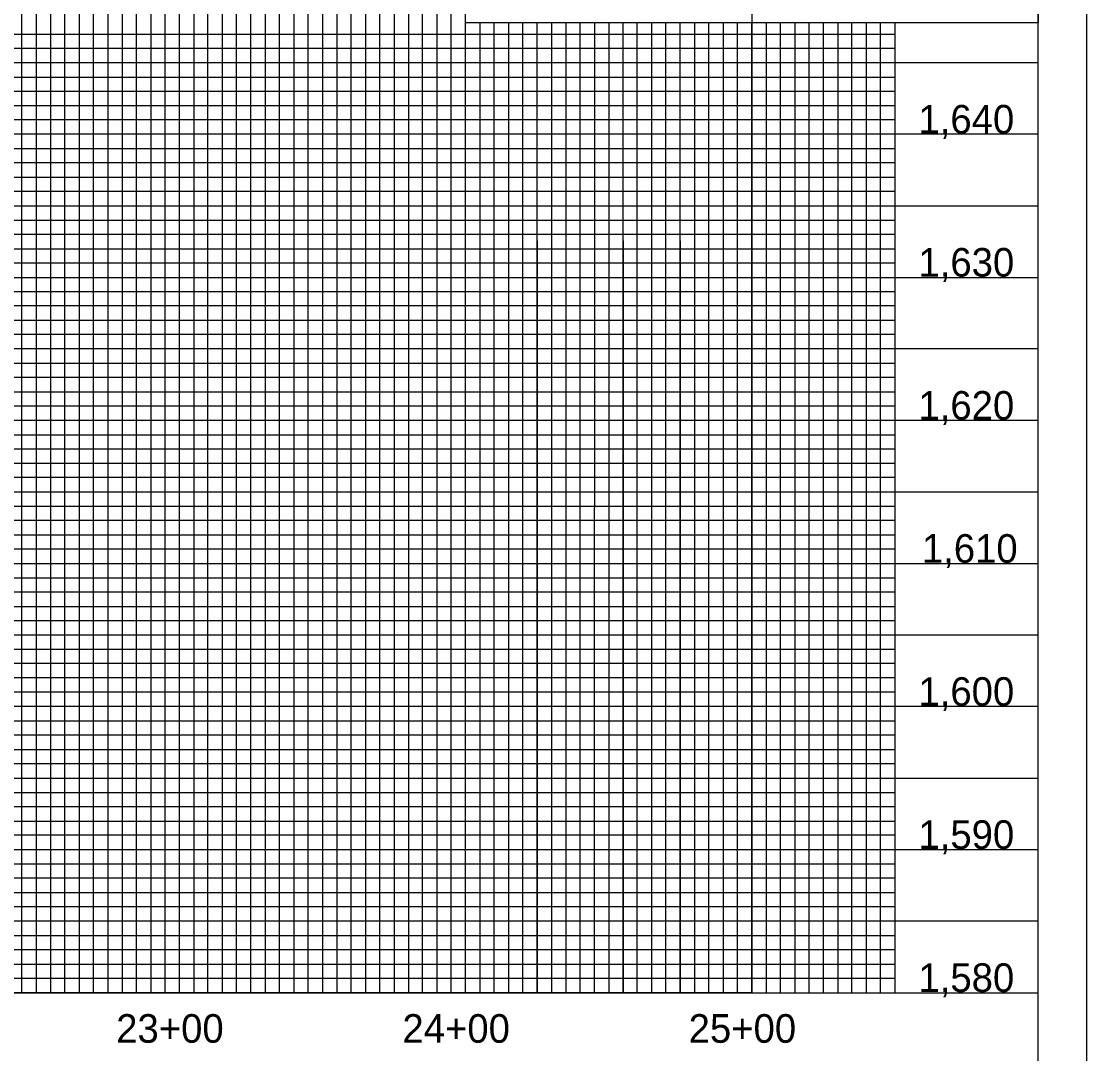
# Model space of a CAD drawing. Extents: x 502400 to 509344, y 448070 to 484209.
# Drawn here: x 506913.9 to 507286.1, y 483662.4 to 484023.2 of the extents above; entities that cross this region are included whole.
import ezdxf

# ---------------------------------------------------------------- set-up
doc = ezdxf.new("R2010")
doc.units = 0
for name, color, linetype in [('Exist Vertical Profile Vertical Axis Label', 7, 'Continuous'), ('Sheet Layout Profile Border Port 1', 7, 'Continuous'), ('Sheet Plot Border Outside CELL', 7, 'Continuous'), ('Sheet Profile CELL', 7, 'Continuous'), ('Sheet Profile Grid Major CELL', 7, 'Continuous'), ('Sheet Profile Grid Middle CELL', 7, 'Continuous'), ('Sheet Profile Grid Minor CELL', 7, 'Continuous'), ('Sheet Sticker Exception Certification CELL', 7, 'Continuous')]:
    doc.layers.add(name, color=color, linetype=linetype)

msp = doc.modelspace()

# ---------------------------------------------------------------- linework, layer by layer
at = {"layer": 'Sheet Layout Profile Border Port 1'}
msp.add_lwpolyline([(506419.08, 484183.71), (507169.08, 484183.71), (507169.08, 483683.71), (506419.08, 483683.71)], close=True, dxfattribs=at)
at = {"layer": 'Sheet Plot Border Outside CELL'}
msp.add_lwpolyline([(505602.08, 483108.71), (507286.08, 483108.71), (507286.08, 484208.71), (505602.08, 484208.71)], close=True, dxfattribs=at)
at = {"layer": 'Sheet Profile CELL'}
msp.add_line((505769.08, 483683.71), (507269.08, 483683.71), dxfattribs=at)
msp.add_lwpolyline([(507269.08, 484183.71), (505769.08, 484183.71), (505769.08, 483133.71), (507269.08, 483133.71)], close=True, dxfattribs=at)
at = {"layer": 'Sheet Profile Grid Major CELL'}
for points in [[(506519.08, 483683.71), (506569.08, 483683.71), (506569.08, 484183.71), (506619.08, 484183.71), (506619.08, 483683.71), (506669.08, 483683.71), (506669.08, 484183.71), (506719.08, 484183.71), (506719.08, 483683.71), (506769.08, 483683.71), (506769.08, 484183.71), (506819.08, 484183.71), (506819.08, 483683.71), (506869.08, 483683.71), (506869.08, 484183.71), (506919.08, 484183.71), (506919.08, 483683.71), (506969.08, 483683.71), (506969.08, 484183.71), (507019.08, 484183.71), (507019.08, 483683.71), (507069.08, 483683.71), (507069.08, 484183.71), (507095.38, 484183.71)], [(507219.08, 484022.66), (507219.08, 483683.71), (507269.08, 483683.71), (507269.08, 484033.71)], [(507119.08, 484022.66), (507119.08, 483683.71), (507169.08, 483683.71), (507169.08, 483683.71), (507169.08, 484022.66)], [(507269.08, 483983.71), (505769.08, 483983.71), (505769.08, 483933.71), (507269.08, 483933.71)], [(507269.08, 483883.71), (505769.08, 483883.71), (505769.08, 483833.71), (507269.08, 483833.71)], [(507269.08, 483783.71), (505769.08, 483783.71), (505769.08, 483783.71), (505769.08, 483733.71), (507269.08, 483733.71)]]:
    msp.add_lwpolyline(points, dxfattribs=at)
at = {"layer": 'Sheet Profile Grid Middle CELL'}
for points in [[(506894.08, 484183.71), (506944.08, 484183.71), (506944.08, 483683.71), (506994.08, 483683.71), (506994.08, 484183.71), (507044.08, 484183.71), (507044.08, 483683.71), (507094.08, 483683.71), (507094.08, 484022.66)], [(507094.08, 483946.51), (507094.08, 483683.71), (507144.08, 483683.71), (507144.08, 484022.66)], [(507144.08, 483946.51), (507144.08, 483683.71), (507194.08, 483683.71), (507194.08, 484022.66)], [(507269.08, 484008.71), (505769.08, 484008.71), (505769.08, 483958.71), (507094.08, 483958.71)], [(507094.08, 483958.71), (507269.08, 483958.71)], [(507269.08, 483908.71), (505769.08, 483908.71), (505769.08, 483858.71), (507269.08, 483858.71)], [(507269.08, 483808.71), (505769.08, 483808.71), (505769.08, 483758.71), (507269.08, 483758.71)], [(507269.08, 483708.71), (505769.08, 483708.71)]]:
    msp.add_lwpolyline(points, dxfattribs=at)
at = {"layer": 'Sheet Profile Grid Minor CELL'}
for p, q in [((505819.08, 484018.71), (507219.08, 484018.71)), ((507219.08, 483998.71), (505819.08, 483998.71)), ((505819.08, 483993.71), (507219.08, 483993.71)), ((507219.08, 483973.71), (505819.08, 483973.71)), ((505819.08, 483968.71), (507219.08, 483968.71)), ((507219.08, 483948.71), (505819.08, 483948.71)), ((505819.08, 483943.71), (507219.08, 483943.71)), ((507219.08, 483938.71), (505819.08, 483938.71)), ((505819.08, 483928.71), (507219.08, 483928.71)), ((507219.08, 483923.71), (505819.08, 483923.71)), ((505819.08, 483918.71), (507219.08, 483918.71)), ((507219.08, 483913.71), (505819.08, 483913.71)), ((505819.08, 483903.71), (507219.08, 483903.71)), ((507219.08, 483898.71), (505819.08, 483898.71)), ((505819.08, 483893.71), (507219.08, 483893.71)), ((507219.08, 483888.71), (505819.08, 483888.71)), ((505819.08, 483878.71), (507219.08, 483878.71)), ((507219.08, 483873.71), (505819.08, 483873.71)), ((505819.08, 483868.71), (507219.08, 483868.71)), ((507219.08, 483863.71), (505819.08, 483863.71)), ((505819.08, 483853.71), (507219.08, 483853.71)), ((507219.08, 483848.71), (505819.08, 483848.71)), ((505819.08, 483843.71), (507219.08, 483843.71)), ((507219.08, 483838.71), (505819.08, 483838.71)), ((505819.08, 483828.71), (507219.08, 483828.71)), ((507219.08, 483823.71), (505819.08, 483823.71)), ((505819.08, 483818.71), (507219.08, 483818.71)), ((507219.08, 483813.71), (505819.08, 483813.71)), ((505819.08, 483803.71), (507219.08, 483803.71)), ((507219.08, 483798.71), (505819.08, 483798.71)), ((507219.08, 483793.71), (505819.08, 483793.71)), ((507219.08, 483788.71), (505819.08, 483788.71)), ((505819.08, 483778.71), (507219.08, 483778.71)), ((507219.08, 483773.71), (505819.08, 483773.71)), ((505819.08, 483768.71), (507219.08, 483768.71)), ((507219.08, 483763.71), (505819.08, 483763.71)), ((505819.08, 483753.71), (507219.08, 483753.71)), ((507219.08, 483748.71), (505819.08, 483748.71)), ((505819.08, 483743.71), (507219.08, 483743.71)), ((507219.08, 483738.71), (505819.08, 483738.71)), ((505819.08, 483728.71), (507219.08, 483728.71)), ((507219.08, 483723.71), (505819.08, 483723.71)), ((505819.08, 483718.71), (507219.08, 483718.71)), ((507219.08, 483713.71), (505819.08, 483713.71)), ((505819.08, 483703.71), (507219.08, 483703.71)), ((507219.08, 483698.71), (505819.08, 483698.71)), ((505819.08, 483693.71), (507219.08, 483693.71))]:
    msp.add_line(p, q, dxfattribs=at)
for points in [[(506909.08, 483683.71), (506914.08, 483683.71), (506914.08, 484183.71), (506924.08, 484183.71), (506924.08, 483683.71), (506929.08, 483683.71), (506929.08, 484183.71), (506934.08, 484183.71), (506934.08, 483683.71), (506939.08, 483683.71), (506939.08, 484183.71), (506949.08, 484183.71), (506949.08, 483683.71), (506954.08, 483683.71), (506954.08, 484183.71), (506959.08, 484183.71), (506959.08, 483683.71)], [(506959.08, 483683.71), (506964.08, 483683.71), (506964.08, 484183.71)], [(506974.08, 484183.71), (506974.08, 483683.71), (506979.08, 483683.71), (506979.08, 484183.71)], [(506984.08, 484183.71), (506984.08, 483683.71), (506989.08, 483683.71), (506989.08, 484183.71)], [(506999.08, 484183.71), (506999.08, 483683.71), (507004.08, 483683.71), (507004.08, 484183.71)], [(507009.08, 484183.71), (507009.08, 483683.71), (507014.08, 483683.71), (507014.08, 484183.71)], [(507024.08, 484183.71), (507024.08, 483683.71), (507029.08, 483683.71), (507029.08, 484183.71)], [(507034.08, 484183.71), (507034.08, 483683.71), (507039.08, 483683.71), (507039.08, 484183.71)], [(507049.08, 484183.71), (507049.08, 483683.71), (507054.08, 483683.71), (507054.08, 484183.71)], [(507059.08, 484183.71), (507059.08, 483683.71), (507064.08, 483683.71), (507064.08, 484183.71)], [(507074.08, 484022.66), (507074.08, 483683.71), (507079.08, 483683.71), (507079.08, 484022.66)], [(507084.08, 484022.66), (507084.08, 483683.71), (507089.08, 483683.71), (507089.08, 484022.66)], [(507099.08, 484022.66), (507099.08, 483683.71), (507099.08, 483683.71), (507104.08, 483683.71), (507109.08, 483683.71), (507109.08, 484022.66)], [(507104.08, 484022.66), (507104.08, 483683.71)], [(507114.07, 484022.66), (507113.98, 483683.76), (507118.98, 483683.76), (507124.08, 483683.71), (507124.08, 484022.66)], [(507124.08, 483946.51), (507124.08, 483683.71), (507129.08, 483683.71), (507129.08, 484022.66)], [(507134.08, 484022.66), (507134.08, 483683.71), (507139.08, 483683.71), (507139.08, 484022.66)], [(507149.08, 484022.66), (507149.08, 483683.71), (507154.08, 483683.71), (507154.08, 484022.66)], [(507159.08, 484022.66), (507159.08, 483683.71), (507164.08, 483683.71), (507164.08, 484022.66)], [(507174.08, 484022.66), (507174.08, 483683.71), (507179.08, 483683.71), (507179.08, 484022.66)], [(507184.08, 484022.66), (507184.08, 483683.71), (507189.08, 483683.71), (507189.08, 484022.66)], [(507199.08, 484022.66), (507199.08, 483683.71), (507204.08, 483683.71), (507204.08, 484022.66)], [(507209.08, 484022.66), (507209.08, 483683.71), (507214.08, 483683.71), (507214.08, 484022.66)], [(507219.08, 484013.71), (505819.08, 484013.71), (505819.08, 484003.71), (507219.08, 484003.71)], [(507219.08, 483988.71), (505819.08, 483988.71), (505819.08, 483978.71), (507219.08, 483978.71)], [(507219.08, 483963.71), (505819.08, 483963.71), (505819.08, 483953.71), (507219.08, 483953.71)], [(507219.08, 483688.71), (505819.08, 483688.71)]]:
    msp.add_lwpolyline(points, dxfattribs=at)
at = {"layer": 'Sheet Sticker Exception Certification CELL'}
for p, q in [((507069.03, 484022.66), (507069.03, 484046.16)), ((507069.03, 484022.66), (507069.03, 484046.16)), ((507269.07, 484046.15), (507269.07, 484022.65)), ((507269.07, 484046.15), (507269.07, 484022.65)), ((507269.07, 484022.66), (507069.03, 484022.66)), ((507269.07, 484022.66), (507069.03, 484022.66))]:
    msp.add_line(p, q, dxfattribs=at)

# ---------------------------------------------------------------- texts
at = {"layer": 'Exist Vertical Profile Vertical Axis Label'}
for s, p in [('1,640', (507227.3, 483983.96)), ('1,630', (507227.3, 483933.96)), ('1,620', (507227.3, 483883.96)), ('1,610', (507228.5, 483833.96)), ('1,600', (507227.3, 483783.96)), ('1,590', (507227.3, 483733.96)), ('1,580', (507227.3, 483683.96)), ('23+00', (506947.01, 483666.21)), ('24+00', (507047.01, 483666.21)), ('25+00', (507147.01, 483666.21))]:
    msp.add_text(s, height=10, dxfattribs=at).set_placement(p)

doc.saveas('drawing.dxf')
